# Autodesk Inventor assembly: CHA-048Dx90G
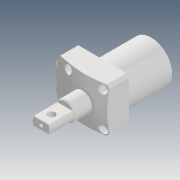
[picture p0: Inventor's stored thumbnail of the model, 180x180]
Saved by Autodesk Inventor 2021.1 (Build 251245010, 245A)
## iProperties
Created: 2019-12
Part Number: CHA-048Dx90G
Description: STEP AP203
Document SubType Name: Assembly
Designer: user
Title: CHA-048Dx90G.STEP
Revision Number: ÈÎºÎ
Sending System: SolidWorks 2017
Preprocessor: SwSTEP 2.0
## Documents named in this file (4)
- D:\Vault_2016\Projekty\Clamptek\Hydraulic\CHA\CHA\CHA-048\Inventor\CHA-048Dx90G\CHA-048Dx90G.iam
- D:\Vault_2016\Projekty\Clamptek\Hydraulic\CHA\CHA\CHA-048\Inventor\CHA-048Dx90G\CHA-048±¾Ìå.ipt
- D:\Vault_2016\Projekty\Clamptek\Hydraulic\CHA\CHA\CHA-048\Inventor\CHA-048Dx90G\CHA-048D(Ë«±Û£©»îÈû¸Ë.ipt
- D:\Vault_2016\Projekty\Clamptek\Hydraulic\CHA\CHA\CHA-048\Inventor\CHA-048Dx90G\G1-8¶ÂÍ·.ipt
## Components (4 placed, 4 different names)
1. CHA-048±¾Ìå_1
2. CHA-048D(Ë«±Û£©»îÈû¸Ë_2
3. G1-8¶ÂÍ·_3
4. G1-8¶ÂÍ·_4
